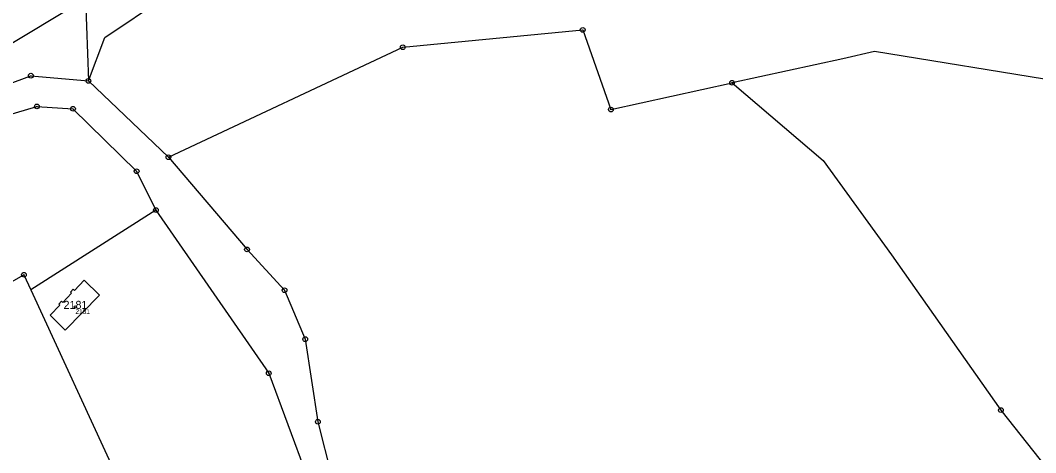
# Model space of a CAD drawing. Extents: x -869390 to -864576, y -1040967 to -1036941.
# Drawn here: x -867616.7 to -867401.1, y -1039671.4 to -1039579.6 of the extents above; entities that cross this region are included whole.
import ezdxf

# ---------------------------------------------------------------- set-up
doc = ezdxf.new("R2010")
doc.units = 0
for name, color, linetype in [('Definiční body', 7, 'Continuous'), ('Hranice parcel', 7, 'Continuous'), ('Parcelní čísla', 7, 'Continuous'), ('Značky bodu BP', 7, 'Continuous')]:
    doc.layers.add(name, color=color, linetype=linetype)

msp = doc.modelspace()

# ---------------------------------------------------------------- linework, layer by layer
at = {"layer": 'Definiční body'}
msp.add_circle((-867604.97, -1039640.43), 0.25, dxfattribs=at)
at = {"layer": 'Hranice parcel'}
for p, q in [((-867598.75, -1039583.26), (-867581.79, -1039571.89)), ((-867666.67, -1039613.64), (-867602.83, -1039575.05)), ((-867602.83, -1039575.05), (-867602.23, -1039592.51)), ((-867535.47, -1039585.36), (-867497.27, -1039581.68)), ((-867497.27, -1039581.68), (-867491.27, -1039598.58)), ((-867602.23, -1039592.51), (-867598.75, -1039583.26)), ((-867585.22, -1039608.68), (-867535.47, -1039585.36)), ((-867435.28, -1039586.23), (-867442.03, -1039587.79)), ((-867391.38, -1039593.41), (-867435.28, -1039586.23)), ((-867442.03, -1039587.79), (-867465.55, -1039592.89)), ((-867630, -1039597.15), (-867614.44, -1039591.39)), ((-867614.44, -1039591.39), (-867602.23, -1039592.51)), ((-867602.23, -1039592.51), (-867585.22, -1039608.68)), ((-867491.27, -1039598.58), (-867465.55, -1039592.89)), ((-867465.55, -1039592.89), (-867446.19, -1039609.39)), ((-867628.05, -1039602.34), (-867613.16, -1039597.9)), ((-867613.16, -1039597.9), (-867605.49, -1039598.42)), ((-867605.49, -1039598.42), (-867591.97, -1039611.65)), ((-867585.22, -1039608.68), (-867568.54, -1039628.25)), ((-867446.19, -1039609.39), (-867431.68, -1039629.42)), ((-867591.97, -1039611.65), (-867587.88, -1039619.9)), ((-867587.88, -1039619.9), (-867614.43, -1039636.8)), ((-867587.88, -1039619.9), (-867563.92, -1039654.52)), ((-867568.54, -1039628.25), (-867560.57, -1039636.89)), ((-867431.68, -1039629.42), (-867408.48, -1039662.33)), ((-867638.66, -1039646.4), (-867615.9, -1039633.62)), ((-867615.9, -1039633.62), (-867614.43, -1039636.8)), ((-867603.09, -1039634.78), (-867605.19, -1039636.93)), ((-867603.09, -1039634.78), (-867599.87, -1039637.92)), ((-867614.43, -1039636.8), (-867563.79, -1039746.44)), ((-867605.78, -1039637.53), (-867607.68, -1039639.47)), ((-867607.14, -1039645.36), (-867599.87, -1039637.92)), ((-867606.03, -1039637.28), (-867605.44, -1039636.68)), ((-867605.78, -1039637.53), (-867606.03, -1039637.28)), ((-867605.44, -1039636.68), (-867605.19, -1039636.93)), ((-867560.57, -1039636.89), (-867556.19, -1039647.28)), ((-867610.36, -1039642.22), (-867608.26, -1039640.07)), ((-867607.93, -1039639.23), (-867608.51, -1039639.83)), ((-867608.51, -1039639.83), (-867608.26, -1039640.07)), ((-867607.68, -1039639.47), (-867607.93, -1039639.23)), ((-867610.36, -1039642.22), (-867607.14, -1039645.36)), ((-867556.19, -1039647.28), (-867553.49, -1039664.81)), ((-867563.92, -1039654.52), (-867554.23, -1039680.48)), ((-867408.48, -1039662.33), (-867391.26, -1039684.07)), ((-867553.49, -1039664.81), (-867550.02, -1039678.44))]:
    msp.add_line(p, q, dxfattribs=at)
at = {"layer": 'Značky bodu BP'}
for centre, radius in [((-867497.27, -1039581.68), 0.5), ((-867497.27, -1039581.68), 0.0303), ((-867535.47, -1039585.36), 0.5), ((-867535.47, -1039585.36), 0.0303), ((-867614.44, -1039591.39), 0.5), ((-867614.44, -1039591.39), 0.0303), ((-867602.23, -1039592.51), 0.5), ((-867602.23, -1039592.51), 0.0303), ((-867465.55, -1039592.89), 0.5), ((-867465.55, -1039592.89), 0.0303), ((-867613.16, -1039597.9), 0.5), ((-867613.16, -1039597.9), 0.0303), ((-867605.49, -1039598.42), 0.5), ((-867605.49, -1039598.42), 0.0303), ((-867491.27, -1039598.58), 0.5), ((-867491.27, -1039598.58), 0.0303), ((-867585.22, -1039608.68), 0.5), ((-867585.22, -1039608.68), 0.0303), ((-867591.97, -1039611.65), 0.5), ((-867591.97, -1039611.65), 0.0303), ((-867587.88, -1039619.9), 0.5), ((-867587.88, -1039619.9), 0.0303), ((-867568.54, -1039628.25), 0.5), ((-867568.54, -1039628.25), 0.0303), ((-867615.9, -1039633.62), 0.5), ((-867615.9, -1039633.62), 0.0303), ((-867560.57, -1039636.89), 0.5), ((-867560.57, -1039636.89), 0.0303), ((-867556.19, -1039647.28), 0.5), ((-867556.19, -1039647.28), 0.0303), ((-867563.92, -1039654.52), 0.5), ((-867563.92, -1039654.52), 0.0303), ((-867408.48, -1039662.33), 0.5), ((-867408.48, -1039662.33), 0.0303), ((-867553.49, -1039664.81), 0.5), ((-867553.49, -1039664.81), 0.0303)]:
    msp.add_circle(centre, radius, dxfattribs=at)

# ---------------------------------------------------------------- texts
at = {"layer": 'Definiční body'}
msp.add_text('2181', height=1, dxfattribs=at).set_placement((-867604.97, -1039641.92))
at = {"layer": 'Parcelní čísla'}
msp.add_text('2181', height=1.7, dxfattribs=at).set_placement((-867607.49, -1039640.85))

doc.saveas('drawing.dxf')
